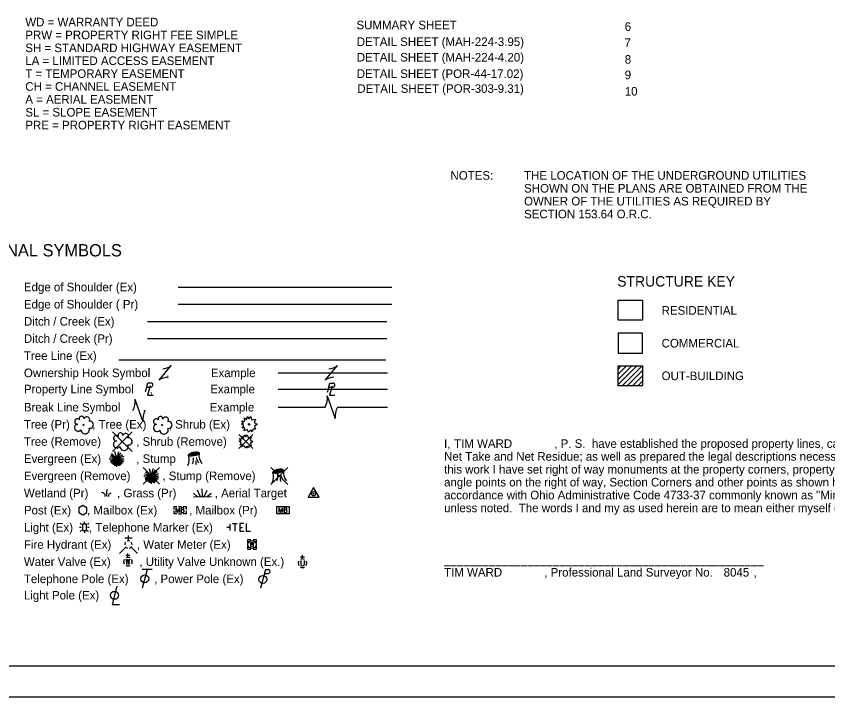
# Model space of a CAD drawing. Extents: x 0 to 34, y 0 to 22.
# Drawn here: x 8.18 to 21.41, y 0 to 11.1 of the extents above; entities that cross this region are included whole.
import ezdxf

# ---------------------------------------------------------------- set-up
doc = ezdxf.new("R2010")
doc.units = 0
for name, color, linetype in [('SC_Shading1', 7, 'Continuous'), ('SH_Border', 7, 'Continuous'), ('SH_Cut_Line', 7, 'Continuous'), ('SH_Data', 7, 'Continuous'), ('SH_Text', 7, 'Continuous')]:
    doc.layers.add(name, color=color, linetype=linetype)

msp = doc.modelspace()

# ---------------------------------------------------------------- linework, layer by layer
at = {"layer": 'SC_Shading1'}
msp.add_lwpolyline([(17.991, 5.608), (18.388, 5.608), (18.388, 5.933), (17.991, 5.933)], close=True, dxfattribs=at)
at = {"layer": 'SH_Border'}
msp.add_lwpolyline([(1.5, 21.5), (33.5, 21.5), (33.5, 0.5), (1.5, 0.5)], close=True, dxfattribs=at)
at = {"layer": 'SH_Cut_Line'}
msp.add_lwpolyline([(0, 0), (34, 0), (34, 22), (0, 22)], close=True, dxfattribs=at)
at = {"layer": 'SH_Text'}
for p, q in [((10.82, 6.684), (14.304, 6.684)), ((10.82, 6.404), (14.304, 6.404)), ((10.32, 6.124), (14.22, 6.124)), ((10.32, 5.844), (14.22, 5.844)), ((9.852, 5.494), (14.202, 5.494)), ((10.507, 5.164), (10.707, 5.404)), ((13.215, 5.164), (13.415, 5.404)), ((17.991, 5.397), (17.993, 5.398)), ((17.991, 5.347), (18.043, 5.398)), ((17.991, 5.262), (18.128, 5.398)), ((17.991, 5.177), (18.212, 5.398)), ((17.991, 5.093), (18.297, 5.398)), ((18.056, 5.072), (18.382, 5.398)), ((18.14, 5.072), (18.388, 5.32)), ((10.607, 5.284), (10.607, 5.284)), ((12.45, 5.284), (14.232, 5.284)), ((13.315, 5.284), (13.315, 5.284)), ((18.225, 5.072), (18.388, 5.236)), ((10.307, 5.053), (10.372, 5.053)), ((13.273, 5.049), (13.338, 5.049)), ((17.991, 5.077), (17.996, 5.072)), ((18.31, 5.072), (18.388, 5.151)), ((10.348, 5.022), (10.348, 5.022)), ((12.45, 5.02), (14.232, 5.02)), ((13.25, 4.908), (13.38, 4.54)), ((13.313, 5.018), (13.313, 5.018)), ((10.115, 4.853), (10.245, 4.484)), ((10.18, 4.669), (10.18, 4.669)), ((12.45, 4.724), (13.215, 4.724)), ((13.315, 4.724), (13.315, 4.724)), ((13.415, 4.724), (14.232, 4.724)), ((9.748, 4.324), (10.068, 4.004)), ((10.068, 4.324), (9.748, 4.004)), ((11.807, 4.28), (12.038, 4.048)), ((12.038, 4.28), (11.807, 4.048)), ((9.908, 4.164), (9.908, 4.164)), ((11.923, 4.164), (11.923, 4.164)), ((9.818, 3.884), (9.731, 3.971)), ((9.818, 3.884), (9.788, 3.999)), ((9.818, 3.884), (9.85, 4.001)), ((9.818, 3.884), (9.885, 3.981)), ((9.695, 3.884), (9.818, 3.884)), ((9.818, 3.884), (9.708, 3.914)), ((9.818, 3.884), (9.711, 3.845)), ((9.818, 3.884), (9.719, 3.827)), ((9.818, 3.884), (9.721, 3.941)), ((9.818, 3.884), (9.721, 3.809)), ((9.818, 3.884), (9.745, 3.797)), ((9.818, 3.884), (9.76, 3.784)), ((9.818, 3.884), (9.777, 3.775)), ((9.818, 3.884), (9.787, 3.763)), ((9.818, 3.884), (9.805, 3.769)), ((9.818, 3.884), (9.91, 3.954)), ((9.818, 3.884), (9.937, 3.924)), ((9.818, 3.884), (9.931, 3.886)), ((9.818, 3.753), (9.818, 3.884)), ((9.818, 3.884), (9.841, 3.768)), ((9.818, 3.884), (9.867, 3.767)), ((9.818, 3.884), (9.882, 3.789)), ((9.818, 3.884), (9.908, 3.796)), ((9.818, 3.884), (9.914, 3.82)), ((9.818, 3.884), (9.93, 3.835)), ((9.818, 3.884), (9.939, 3.86)), ((11.092, 3.884), (11.092, 3.884)), ((10.249, 3.738), (10.516, 3.47)), ((10.516, 3.738), (10.249, 3.47)), ((10.382, 3.604), (10.352, 3.719)), ((10.382, 3.604), (10.414, 3.722)), ((12.329, 3.743), (12.607, 3.465)), ((12.607, 3.743), (12.329, 3.465)), ((10.259, 3.604), (10.382, 3.604)), ((10.382, 3.604), (10.272, 3.634)), ((10.382, 3.604), (10.275, 3.565)), ((10.382, 3.604), (10.283, 3.547)), ((10.382, 3.604), (10.285, 3.662)), ((10.382, 3.604), (10.285, 3.529)), ((10.382, 3.604), (10.295, 3.691)), ((10.382, 3.604), (10.309, 3.517)), ((10.382, 3.604), (10.324, 3.504)), ((10.382, 3.604), (10.341, 3.496)), ((10.382, 3.604), (10.351, 3.483)), ((10.382, 3.604), (10.369, 3.489)), ((10.382, 3.604), (10.449, 3.701)), ((10.382, 3.604), (10.474, 3.674)), ((10.382, 3.604), (10.501, 3.644)), ((10.382, 3.604), (10.495, 3.606)), ((10.382, 3.473), (10.382, 3.604)), ((10.382, 3.604), (10.405, 3.488)), ((10.382, 3.604), (10.431, 3.487)), ((10.382, 3.604), (10.446, 3.509)), ((10.382, 3.604), (10.472, 3.516)), ((10.382, 3.604), (10.478, 3.54)), ((10.382, 3.604), (10.494, 3.556)), ((10.382, 3.604), (10.503, 3.58)), ((10.382, 3.604), (10.382, 3.604)), ((12.468, 3.604), (12.468, 3.604)), ((12.468, 3.604), (12.468, 3.604)), ((11.135, 3.263), (11.067, 3.32)), ((11.184, 3.264), (11.132, 3.37)), ((11.214, 3.264), (11.212, 3.39)), ((11.244, 3.265), (11.293, 3.372)), ((11.293, 3.265), (11.359, 3.324)), ((11.068, 3.262), (11.36, 3.266)), ((10.825, 3.105), (10.875, 3.105)), ((10.851, 3.044), (10.851, 3.044)), ((12.529, 3.044), (12.529, 3.044)), ((10.825, 2.983), (10.875, 2.983)), ((9.243, 2.813), (9.224, 2.831)), ((9.291, 2.828), (9.291, 2.855)), ((9.358, 2.831), (9.339, 2.813)), ((11.664, 2.714), (11.664, 2.814)), ((9.239, 2.764), (9.212, 2.764)), ((9.243, 2.716), (9.224, 2.697)), ((9.291, 2.764), (9.291, 2.764)), ((9.291, 2.7), (9.291, 2.674)), ((9.358, 2.697), (9.339, 2.716)), ((9.37, 2.764), (9.343, 2.764)), ((11.664, 2.764), (11.614, 2.764)), ((10.069, 2.587), (9.949, 2.587)), ((10.009, 2.544), (10.009, 2.63)), ((9.967, 2.442), (9.863, 2.338)), ((10.009, 2.484), (10.009, 2.484)), ((10.009, 2.484), (10.009, 2.484)), ((10.052, 2.442), (10.156, 2.338)), ((12.023, 2.484), (12.023, 2.484)), ((10.032, 2.306), (9.968, 2.306)), ((10, 2.274), (10, 2.338)), ((12.878, 2.28), (12.814, 2.28)), ((12.846, 2.248), (12.846, 2.311)), ((10, 2.204), (10, 2.204)), ((12.819, 2.221), (12.819, 2.152)), ((12.846, 2.178), (12.846, 2.178)), ((12.873, 2.221), (12.873, 2.152)), ((10.393, 2.074), (10.233, 2.074)), ((10.313, 2.074), (10.233, 1.774)), ((12.242, 2.074), (12.162, 1.774)), ((12.225, 2.01), (12.285, 2.01)), ((12.242, 2.074), (12.285, 2.074))]:
    msp.add_line(p, q, dxfattribs=at)
for points in [[(17.991, 6.469), (18.388, 6.469), (18.388, 6.143), (17.991, 6.143)], [(17.991, 5.398), (18.388, 5.398), (18.388, 5.072), (17.991, 5.072)], [(12.937, 3.254), (13.117, 3.254), (13.027, 3.415)], [(12.429, 3.105), (12.629, 3.105), (12.629, 2.983), (12.429, 2.983)], [(9.258, 2.714), (9.324, 2.714), (9.324, 2.814), (9.258, 2.814)]]:
    msp.add_lwpolyline(points, close=True, dxfattribs=at)
for points in [[(10.286, 4.974), (10.326, 5.122), (10.377, 5.122)], [(10.361, 5.07), (10.321, 4.922), (10.409, 4.922)], [(13.252, 4.969), (13.291, 5.118), (13.343, 5.118)], [(13.327, 5.066), (13.287, 4.918), (13.374, 4.918)], [(11.971, 4.535), (12.002, 4.571), (12.022, 4.519), (12.077, 4.528), (12.06, 4.477), (12.107, 4.447), (12.064, 4.411), (12.077, 4.365), (12.039, 4.368), (12.023, 4.323), (12.002, 4.357), (11.968, 4.316), (11.946, 4.361), (11.895, 4.339), (11.905, 4.386), (11.864, 4.382), (11.888, 4.422), (11.849, 4.45), (11.886, 4.463), (11.856, 4.503), (11.903, 4.498), (11.901, 4.55), (11.939, 4.521), (11.949, 4.571), (11.971, 4.535)], [(11.919, 4.241), (11.945, 4.272), (11.962, 4.228), (12.009, 4.235), (11.994, 4.192), (12.034, 4.167), (11.998, 4.136), (12.009, 4.097), (11.977, 4.1), (11.963, 4.061), (11.945, 4.09), (11.916, 4.056), (11.898, 4.093), (11.854, 4.075), (11.862, 4.115), (11.828, 4.112), (11.848, 4.145), (11.815, 4.169), (11.847, 4.18), (11.821, 4.215), (11.861, 4.21), (11.859, 4.254), (11.891, 4.23), (11.9, 4.272), (11.919, 4.241)], [(9.198, 3.007), (9.263, 2.969), (9.328, 3.007), (9.328, 3.082), (9.263, 3.119), (9.198, 3.082), (9.198, 3.007)], [(10.751, 3.057), (10.751, 3.105), (10.799, 3.105)], [(10.786, 3.004), (10.786, 3.084), (10.815, 3.004), (10.843, 3.084), (10.843, 3.004)], [(10.902, 3.048), (10.905, 3.051), (10.907, 3.053), (10.908, 3.055), (10.909, 3.056), (10.91, 3.058), (10.911, 3.06), (10.912, 3.065), (10.912, 3.067), (10.912, 3.069), (10.911, 3.073), (10.91, 3.076), (10.908, 3.078), (10.905, 3.081), (10.903, 3.082), (10.901, 3.083), (10.898, 3.084), (10.867, 3.084), (10.867, 3.004), (10.902, 3.004), (10.906, 3.007), (10.91, 3.01), (10.913, 3.015), (10.915, 3.021), (10.916, 3.026), (10.916, 3.03), (10.914, 3.034), (10.912, 3.039), (10.909, 3.043), (10.902, 3.048), (10.867, 3.048)], [(10.901, 3.105), (10.951, 3.105), (10.951, 3.057)], [(12.464, 3.004), (12.464, 3.084), (12.493, 3.004), (12.521, 3.084), (12.521, 3.004)], [(12.58, 3.048), (12.583, 3.051), (12.585, 3.053), (12.586, 3.055), (12.587, 3.056), (12.588, 3.058), (12.589, 3.06), (12.59, 3.065), (12.59, 3.067), (12.59, 3.069), (12.589, 3.073), (12.588, 3.076), (12.586, 3.078), (12.583, 3.081), (12.581, 3.082), (12.579, 3.083), (12.576, 3.084), (12.545, 3.084), (12.545, 3.004), (12.58, 3.004), (12.584, 3.007), (12.588, 3.01), (12.591, 3.015), (12.593, 3.021), (12.594, 3.026), (12.594, 3.03), (12.593, 3.034), (12.59, 3.039), (12.587, 3.043), (12.58, 3.048), (12.545, 3.048)], [(10.799, 2.983), (10.751, 2.983), (10.751, 3.032)], [(10.951, 3.032), (10.951, 2.983), (10.901, 2.983)], [(11.705, 2.826), (11.782, 2.826)], [(11.744, 2.826), (11.744, 2.701)], [(11.89, 2.826), (11.822, 2.826), (11.822, 2.701), (11.895, 2.701)], [(11.929, 2.826), (11.929, 2.701), (11.997, 2.701)], [(11.822, 2.764), (11.87, 2.764)], [(12.003, 2.559), (11.948, 2.559), (11.948, 2.504)], [(11.989, 2.529), (12.006, 2.439), (12.023, 2.529), (12.039, 2.439), (12.056, 2.529)], [(12.098, 2.504), (12.098, 2.559), (12.043, 2.559)], [(11.948, 2.464), (11.948, 2.409), (12.003, 2.409)], [(12.043, 2.409), (12.098, 2.409), (12.098, 2.464)], [(9.968, 2.245), (9.984, 2.159), (10, 2.245), (10.016, 2.159), (10.032, 2.245)], [(9.82, 1.803), (9.742, 1.504), (9.86, 1.504)]]:
    msp.add_lwpolyline(points, dxfattribs=at)
for centre, radius in [((9.275, 4.436), 0.0084), ((10.56, 4.433), 0.0072), ((11.976, 4.444), 0.0115), ((9.908, 4.164), 0.0072), ((11.923, 4.164), 0.00979), ((13.027, 3.312), 0.035), ((13.027, 3.312), 0.008), ((12.023, 2.484), 0.0675), ((10.273, 1.924), 0.065), ((12.199, 1.914), 0.065), ((9.781, 1.655), 0.065)]:
    msp.add_circle(centre, radius, dxfattribs=at)
for centre, radius, start, end in [((10.549, 5.619), 0.267, 273.6945, 306.337), ((13.257, 5.619), 0.267, 273.6945, 306.337), ((10.665, 4.949), 0.267, 93.6945, 126.337), ((13.373, 4.949), 0.267, 93.6945, 126.337), ((10.372, 5.088), 0.0345, 270.471, 81.3281), ((13.338, 5.084), 0.0345, 270.471, 81.3281), ((12.918, 4.876), 0.334, 332.9422, 5.5848), ((9.783, 4.82), 0.334, 332.9422, 5.5848), ((10.577, 4.517), 0.334, 152.9422, 185.5848), ((13.712, 4.573), 0.334, 152.9422, 185.5848), ((9.176, 4.492), 0.0441, 39.0625, 279.5412), ((9.245, 4.537), 0.0395, 354.0047, 205.9741), ((9.33, 4.521), 0.0466, 323.83, 165.0376), ((10.46, 4.489), 0.0441, 39.0625, 279.5412), ((10.53, 4.534), 0.0395, 354.0047, 205.9741), ((10.614, 4.517), 0.0466, 323.83, 165.0376), ((9.189, 4.39), 0.0592, 96.1722, 320.5737), ((9.303, 4.358), 0.0685, 184.9476, 19.4572), ((9.379, 4.437), 0.0574, 259.1453, 101.4596), ((10.474, 4.386), 0.0592, 96.1722, 320.5737), ((10.588, 4.354), 0.0685, 184.9476, 19.4572), ((10.663, 4.434), 0.0574, 259.1453, 101.4596), ((9.809, 4.22), 0.0441, 39.0625, 279.5412), ((9.878, 4.265), 0.0395, 354.0047, 205.9741), ((9.963, 4.249), 0.0466, 323.83, 165.0376), ((9.822, 4.118), 0.0592, 96.1722, 320.5737), ((9.936, 4.086), 0.0685, 184.9476, 19.4572), ((10.012, 4.165), 0.0574, 259.1453, 101.4596), ((11.372, 3.941), 0.215, 171.4106, 219.9194), ((10.801, 3.867), 0.2, 331.5338, 20.9269), ((10.816, 3.885), 0.253, 340.7938, 3.5481), ((11.287, 3.844), 0.182, 178.7926, 197.1224), ((11.417, 3.987), 0.316, 194.9653, 212.1216), ((12.176, 3.587), 0.2, 331.5338, 20.9269), ((12.192, 3.605), 0.253, 340.7938, 3.5481), ((12.793, 3.707), 0.316, 194.9653, 212.1216), ((12.748, 3.661), 0.215, 171.4106, 219.9194), ((12.663, 3.564), 0.182, 178.7926, 197.1224), ((10.009, 2.484), 0.06, 140.021, 184.0629), ((10.009, 2.484), 0.06, 68.1395, 112.038), ((10.009, 2.484), 0.06, 356.0165, 39.9889), ((10.009, 2.484), 0.06, 211.8788, 255.8479), ((10.009, 2.484), 0.06, 283.8239, 329.9097), ((10, 2.204), 0.07, 60.0184, 120.0157), ((10, 2.204), 0.07, 150.0184, 209.9816), ((10, 2.204), 0.07, 239.9843, 299.9816), ((10, 2.204), 0.07, 330.0184, 29.9816), ((12.846, 2.178), 0.07, 150.0184, 209.9816), ((12.846, 2.178), 0.07, 60.0184, 120.0157), ((12.846, 2.178), 0.07, 239.9843, 299.9816), ((12.846, 2.165), 0.03, 205.1924, 334.8076), ((12.846, 2.178), 0.07, 330.0184, 29.9816), ((12.285, 2.042), 0.0319, 268.8767, 91.1233)]:
    msp.add_arc(centre, radius, start, end, dxfattribs=at)
for centre, major_axis in [((11.073, 3.96), (0.0868, 0.0187)), ((11.073, 3.96), (0.0651, 0.0141)), ((11.073, 3.96), (0.0488, 0.0105)), ((11.073, 3.96), (0.0275, 0.0059)), ((11.073, 3.96), (0.0154, 0.0033)), ((12.449, 3.68), (0.0868, 0.0187)), ((12.449, 3.68), (0.0651, 0.0141)), ((12.449, 3.68), (0.0488, 0.0105)), ((12.449, 3.68), (0.0275, 0.0059)), ((12.449, 3.68), (0.0154, 0.0033))]:
    msp.add_ellipse(centre, major_axis=major_axis, ratio=0.36865, dxfattribs=at)
for points in [[(9.567, 3.34), (9.609, 3.322), (9.626, 3.269)], [(9.655, 3.273), (9.655, 3.32), (9.66, 3.364), (9.669, 3.385)], [(9.682, 3.266), (9.694, 3.304), (9.724, 3.328)]]:
    msp.add_spline(points, degree=3, dxfattribs=at)

# ---------------------------------------------------------------- texts
at = {"layer": 'SH_Data'}
for s, p in [('SUMMARY SHEET', (13.726, 10.889)), ('6', (18.099, 10.863)), ('DETAIL SHEET (MAH-224-3.95)', (13.731, 10.616)), ('7', (18.094, 10.601)), ('DETAIL SHEET (MAH-224-4.20)', (13.731, 10.363)), ('8', (18.099, 10.328)), ('DETAIL SHEET (POR-44-17.02)', (13.731, 10.095)), ('9', (18.099, 10.075)), ('DETAIL SHEET (POR-303-9.31)', (13.739, 9.852)), ('10', (18.099, 9.807))]:
    msp.add_text(s, height=0.14, dxfattribs=at).set_placement(p)
at = {"layer": 'SH_Text'}
for s, height, p in [('WD = WARRANTY DEED', 0.14, (8.327, 10.936)), ('PRW = PROPERTY RIGHT FEE SIMPLE', 0.14, (8.327, 10.726)), ('SH = STANDARD HIGHWAY EASEMENT', 0.14, (8.327, 10.516)), ('LA = LIMITED ACCESS EASEMENT', 0.14, (8.327, 10.306)), ('T = TEMPORARY EASEMENT', 0.14, (8.327, 10.096)), ('CH = CHANNEL EASEMENT', 0.14, (8.327, 9.886)), ('A = AERIAL EASEMENT', 0.14, (8.327, 9.676)), ('SL = SLOPE EASEMENT', 0.14, (8.327, 9.466)), ('PRE = PROPERTY RIGHT EASEMENT', 0.14, (8.327, 9.256)), ('NOTES:', 0.14, (15.258, 8.435)), ('THE LOCATION OF THE UNDERGROUND UTILITIES', 0.14, (16.458, 8.435)), ('SHOWN ON THE PLANS ARE OBTAINED FROM THE', 0.14, (16.458, 8.225)), ('OWNER OF THE UTILITIES AS REQUIRED BY', 0.14, (16.458, 8.015)), ('SECTION 153.64 O.R.C.', 0.14, (16.458, 7.805)), ('CONVENTIONAL SYMBOLS', 0.2, (6.424, 7.184)), ('Edge of Shoulder (Ex)', 0.14, (8.304, 6.614)), ('STRUCTURE KEY', 0.17, (17.976, 6.692)), ('Edge of Shoulder ( Pr)', 0.14, (8.304, 6.334)), ('RESIDENTIAL', 0.14, (18.7, 6.233)), ('Ditch / Creek (Ex)', 0.14, (8.304, 6.054)), ('Ditch / Creek (Pr)', 0.14, (8.304, 5.774)), ('COMMERCIAL', 0.14, (18.7, 5.698)), ('Tree Line (Ex)', 0.14, (8.304, 5.494)), ('Ownership Hook Symbol     ,             Example', 0.14, (8.304, 5.214)), ('OUT-BUILDING', 0.14, (18.7, 5.166)), ('Property Line Symbol     ,                  Example', 0.14, (8.304, 4.95)), ('Break Line Symbol       ,                    Example', 0.14, (8.304, 4.654)), ('Tree (Pr)       , Tree (Ex)       , Shrub (Ex)', 0.14, (8.304, 4.374)), ('Tree (Remove)           , Shrub (Remove)', 0.14, (8.304, 4.094)), ('I, ', 0.14, (15.154, 4.061)), ('TIM WARD            ', 0.14, (15.317, 4.061)), (', P. S.  have established the proposed property lines, calculated the Gross Take, Present Roadway Occupied (PRO),', 0.14, (16.95, 4.061)), ('Net Take and Net Residue; as well as prepared the legal descriptions necessary to acquire these parcels as shown herein. As a part of', 0.14, (15.154, 3.851)), ('Evergreen (Ex)           , Stump ', 0.14, (8.304, 3.814)), ('this work I have set right of way monuments at the property corners, property line intersections, points along the right of way and/or', 0.14, (15.154, 3.641)), ('Evergreen (Remove)          , Stump (Remove)', 0.14, (8.304, 3.534)), ('angle points on the right of way, Section Corners and other points as shown herein.  All of my work contained herein was conducted in', 0.14, (15.154, 3.431)), ('Wetland (Pr)         , Grass (Pr)            , Aerial Target    ', 0.14, (8.304, 3.254)), ('accordance with Ohio Administrative Code 4733-37 commonly known as "Minimum Standards for Boundary Surveys in the State of Ohio"', 0.14, (15.154, 3.221)), ('Post (Ex)     , Mailbox (Ex)          , Mailbox (Pr)', 0.14, (8.304, 2.974)), ('unless noted.  The words I and my as used herein are to mean either myself or someone working under my direct supervision.', 0.14, (15.154, 3.011)), ('Light (Ex)     , Telephone Marker (Ex)     ', 0.14, (8.304, 2.694)), ('Fire Hydrant (Ex)        , Water Meter (Ex)', 0.14, (8.304, 2.414)), ('Water Valve (Ex)         , Utility Valve Unknown (Ex.)', 0.14, (8.304, 2.134)), ('__________________________________________________', 0.14, (15.154, 2.171)), ('Telephone Pole (Ex)        , Power Pole (Ex)', 0.14, (8.304, 1.854)), ('TIM WARD            ', 0.14, (15.154, 1.961)), (', Professional Land Surveyor No. ', 0.14, (16.787, 1.961)), ('8045 ', 0.14, (19.711, 1.961)), (',                                   Date: ', 0.14, (20.2, 1.961)), ('Light Pole (Ex)     ', 0.14, (8.304, 1.587))]:
    msp.add_text(s, height=height, dxfattribs=at).set_placement(p)

doc.saveas('drawing.dxf')
